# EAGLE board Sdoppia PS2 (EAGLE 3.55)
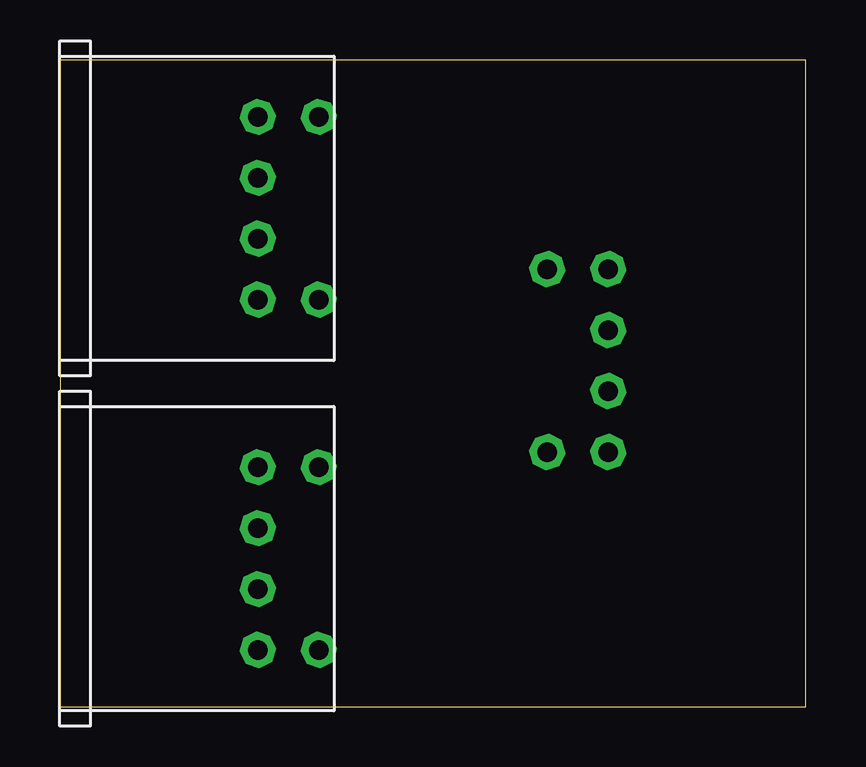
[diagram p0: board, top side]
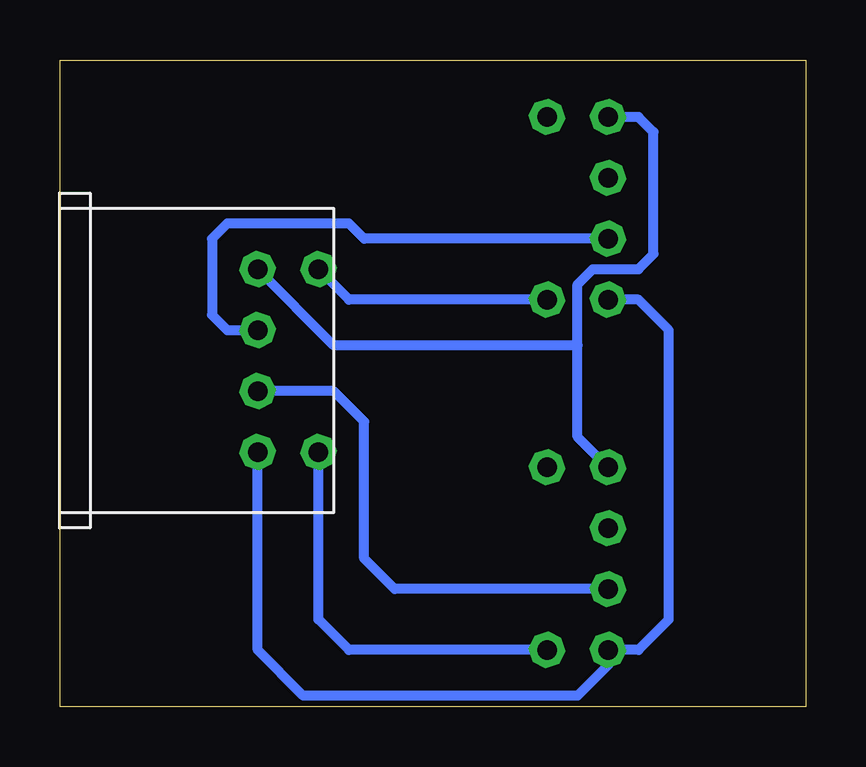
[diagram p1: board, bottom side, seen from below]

Size 31.09 x 26.97 mm. Coordinates in mm from the lower left corner, seen from the top.
Outline: 0,0 31.09,0 31.09,26.97 0,26.97 0,0
Copper layers used: Bottom

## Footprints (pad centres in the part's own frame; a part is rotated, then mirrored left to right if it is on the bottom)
/2 = drill 0.813 pad 1.422 octagon: ATA1 -9.525,0; ATA2 -9.525,-2.54; CC -9.525,-5.08; LK1 -12.065,2.54; LK2 -12.065,-5.08; ND -9.525,2.54

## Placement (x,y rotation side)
CON1  PS/2  [/2]  -1.27,19.52 180 top
CON2  PS/2  [/2]  -1.27,4.92 180 top
CON3  PS/2  [/2]  32.38,13.17 180 bottom

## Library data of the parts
CON1-CON3 = conquick

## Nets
GND: CON1.ND CON2.ND CON3.ND
N$7: CON1.ATA1 CON3.ATA2
N$8: CON2.ATA1 CON3.ATA1
N$9: CON2.LK1 CON3.LK1
N$10: CON1.LK1 CON3.LK2
VCC: CON1.CC CON2.CC CON3.CC

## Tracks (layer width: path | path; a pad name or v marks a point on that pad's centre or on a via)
GND
  Bottom 0.406: CON1.ND 6.98,16.98 5.71,15.71 5.71,3.65 6.98,2.38 CON2.ND 8.25,1.74 9.52,0.47 20.95,0.47 22.86,2.38 CON3.ND
N$7
  Bottom 0.406: CON3.ATA2 24.12,15.71 24.76,16.34 24.76,19.52 24.12,20.15 19.04,20.15 18.41,19.52 CON1.ATA1
N$8
  Bottom 0.406: CON3.ATA1 19.68,13.17 18.41,11.9 18.41,6.19 17.14,4.92 CON2.ATA1
N$9
  Bottom 0.406: CON3.LK1 20.31,3.65 19.04,2.38 CON2.LK1
N$10
  Bottom 0.406: CON1.LK1 19.04,16.98 CON3.LK2
VCC
  Bottom 0.406: CON2.CC 9.52,11.26 9.52,15.07 | 9.52,15.07 9.52,17.61 8.88,18.25 6.98,18.25 6.35,18.88 6.35,23.96 6.98,24.6 CON1.CC | CON3.CC 19.68,15.07 9.52,15.07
